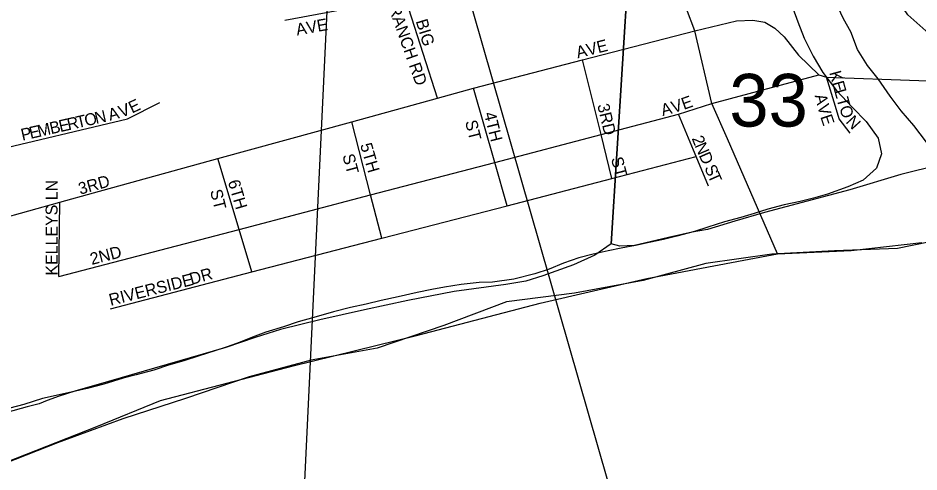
# Model space of a CAD drawing. Extents: x 0 to 34, y 0 to 22.
# Drawn here: x 4.109 to 4.825, y 15.627 to 15.987 of the extents above; entities that cross this region are included whole.
import ezdxf

# ---------------------------------------------------------------- set-up
doc = ezdxf.new("R2010")
doc.units = 0
for name, color, linetype in [('GM_X_City_Street', 7, 'Continuous'), ('GM_X_City_Street_Text', 7, 'Continuous'), ('GM_X_Corporation', 7, 'Continuous'), ('GM_X_County', 7, 'Continuous'), ('GM_X_Major_River', 7, 'Continuous'), ('GM_X_Section', 7, 'Continuous'), ('GM_X_Section_Text', 7, 'Continuous'), ('GM_X_State_Route', 7, 'Continuous'), ('GM_X_Township', 7, 'Continuous'), ('SH_Text', 7, 'Continuous')]:
    doc.layers.add(name, color=color, linetype=linetype)

msp = doc.modelspace()

# ---------------------------------------------------------------- linework, layer by layer
at = {"layer": 'GM_X_City_Street'}
for points in [[(4.86125, 15.93632), (4.85274, 15.94797), (4.84833, 15.95944), (4.83245, 15.97489), (4.81569, 15.9899), (4.80157, 16.01108), (4.79231, 16.02829), (4.78084, 16.05212), (4.76716, 16.07066), (4.75735, 16.07837), (4.75513, 16.07932), (4.7419, 16.085), (4.71334, 16.09156), (4.70852, 16.09155), (4.68605, 16.0915), (4.66482, 16.0903), (4.64496, 16.08968), (4.61963, 16.13871), (4.60617, 16.16446), (4.59926, 16.17803), (4.59104, 16.19418), (4.57912, 16.21207)], [(4.44235, 15.92357), (4.41948, 15.9945), (4.4089, 16.0181), (4.4039, 16.02506), (4.39749, 16.03163), (4.38508, 16.04152), (4.29, 16.06275), (4.24872, 16.07468)], [(4.32117, 15.98558), (4.38685, 15.99761)], [(4.44235, 15.92357), (4.47091, 15.93141), (4.55748, 15.95393), (4.64682, 15.97698)], [(4.58091, 15.85974), (4.57222, 15.89467), (4.55748, 15.95393)], [(4.14169, 15.78179), (4.28486, 15.81933), (4.38928, 15.8467), (4.48786, 15.87256), (4.57222, 15.89467), (4.63377, 15.91081), (4.66031, 15.91938), (4.74515, 15.94209)], [(4.75834, 15.91682), (4.75121, 15.94026)], [(4.49778, 15.83813), (4.48786, 15.87256), (4.47091, 15.93141)], [(4.08456, 15.88074), (4.19618, 15.90713), (4.22201, 15.92)], [(4.09304, 15.82718), (4.1424, 15.84105), (4.16933, 15.84846), (4.26803, 15.87561), (4.3744, 15.90487), (4.44235, 15.92357)], [(4.64568, 15.88228), (4.63377, 15.91081)], [(4.76999, 15.89571), (4.76128, 15.90714), (4.75834, 15.91682)], [(4.39809, 15.81223), (4.38928, 15.8467), (4.3744, 15.90487)], [(4.65758, 15.85374), (4.64782, 15.87712), (4.64568, 15.88228), (4.64568, 15.88228)], [(4.18263, 15.75624), (4.295, 15.78543), (4.39809, 15.81223), (4.49778, 15.83813), (4.58091, 15.85974), (4.64782, 15.87712)], [(4.295, 15.78543), (4.28486, 15.81933), (4.26803, 15.87561)], [(4.14169, 15.78179), (4.1424, 15.84105)]]:
    msp.add_lwpolyline(points, dxfattribs=at)
at = {"layer": 'GM_X_Corporation'}
msp.add_lwpolyline([(4.85824, 15.81444), (4.80773, 15.80402), (4.75763, 15.80234), (4.70791, 15.79952), (4.65552, 15.79216), (4.60575, 15.7787), (4.55106, 15.76868), (4.49715, 15.7617), (4.44736, 15.74292), (4.39453, 15.72492), (4.34213, 15.71527), (4.29274, 15.70219), (4.2422, 15.68494), (4.19242, 15.66882), (4.14073, 15.64967), (4.09056, 15.63014)], dxfattribs=at)
at = {"layer": 'GM_X_County'}
msp.add_lwpolyline([(4.09995, 15.63443), (4.17199, 15.66269), (4.22242, 15.6833), (4.32785, 15.71087), (4.42569, 15.73501), (4.52391, 15.76066), (4.60849, 15.78021), (4.68557, 15.79473), (4.71246, 15.79978), (4.77084, 15.80259), (4.82699, 15.80879)], dxfattribs=at)
at = {"layer": 'GM_X_Major_River'}
for points in [[(4.72161, 16.00319), (4.72848, 15.98423), (4.73343, 15.97134), (4.74067, 15.95693), (4.74828, 15.94405), (4.75929, 15.92966), (4.77183, 15.91603), (4.78283, 15.90505), (4.79233, 15.8918)], [(4.83058, 15.8885), (4.8207, 15.90175), (4.81044, 15.91349), (4.8017, 15.92523), (4.7922, 15.93887), (4.78384, 15.94947), (4.77586, 15.96235), (4.77052, 15.97638), (4.76481, 15.98661), (4.75872, 15.9995)], [(4.79233, 15.8918), (4.79502, 15.87928), (4.79089, 15.86788), (4.78032, 15.85836), (4.76822, 15.85301), (4.75196, 15.84726), (4.74099, 15.84419), (4.7304, 15.8415), (4.71753, 15.83881), (4.70467, 15.83535), (4.6937, 15.8319), (4.68312, 15.82883), (4.67025, 15.82538), (4.65702, 15.82116), (4.64643, 15.81771), (4.63243, 15.81387), (4.62184, 15.81119), (4.61049, 15.80887), (4.59952, 15.80656), (4.58817, 15.80425), (4.57796, 15.80232), (4.56585, 15.79963), (4.5545, 15.79656), (4.5424, 15.79234), (4.53106, 15.78776), (4.51972, 15.78392), (4.50307, 15.7797), (4.48605, 15.77737), (4.47545, 15.77696), (4.46107, 15.7754), (4.44783, 15.77346), (4.43799, 15.77153), (4.42626, 15.76922), (4.41113, 15.76575), (4.39751, 15.76268), (4.38579, 15.75998), (4.3733, 15.75729), (4.35968, 15.75383), (4.34418, 15.74923), (4.3317, 15.74577), (4.31997, 15.74194), (4.30598, 15.73773), (4.29539, 15.73352), (4.28556, 15.72969), (4.27535, 15.72587), (4.26552, 15.7228), (4.25228, 15.71859), (4.24094, 15.71476), (4.22884, 15.7113), (4.21711, 15.70747), (4.20312, 15.70363), (4.19291, 15.70095), (4.1774, 15.69634), (4.16416, 15.69289), (4.15243, 15.6902), (4.14184, 15.68789), (4.1286, 15.68481), (4.11385, 15.68021), (4.10288, 15.67714)]]:
    msp.add_lwpolyline(points, dxfattribs=at)
at = {"layer": 'GM_X_Section'}
for points in [[(3.50743, 16.08595), (4.59377, 16.02271), (4.58028, 15.80787), (4.56741, 15.79876), (4.55036, 15.79118), (4.52613, 15.78245), (4.51249, 15.77826), (4.49657, 15.7756), (4.45566, 15.76989), (4.41891, 15.76266), (4.38444, 15.75544), (4.34882, 15.74745), (4.31776, 15.73985), (4.29769, 15.7334), (4.2742, 15.72542), (4.18101, 15.69846), (4.15449, 15.69086), (4.14199, 15.68668), (4.13252, 15.68327), (4.12608, 15.68061), (4.11661, 15.67833), (4.07911, 15.66807)], [(4.8413, 15.87058), (4.81024, 15.86297), (4.7697, 15.85082), (4.70189, 15.83259), (4.67841, 15.82575), (4.65681, 15.81929), (4.64469, 15.81701), (4.62575, 15.81283), (4.59885, 15.80636), (4.58711, 15.80598), (4.58028, 15.80787), (4.59377, 16.02271), (5.23679, 15.98757)]]:
    msp.add_lwpolyline(points, dxfattribs=at)
at = {"layer": 'GM_X_State_Route'}
for points in [[(4.82457, 15.93763), (4.86125, 15.93632), (4.89421, 15.93426), (4.9215, 15.93426), (4.95086, 15.93499), (4.9678, 15.93881), (4.99473, 15.94584), (5.05575, 15.97631), (5.05991, 15.97837), (5.1536, 16.02489), (5.27058, 16.07147), (5.37835, 16.10837), (5.51744, 16.15908), (5.5266, 16.16226), (5.67496, 16.21375)], [(4.64682, 15.97698), (4.62693, 16.02973), (4.60641, 16.08067), (4.59597, 16.10951), (4.56509, 16.18055)], [(4.64682, 15.97698), (4.6797, 15.98505), (4.69283, 15.98562), (4.7024, 15.98405), (4.71024, 15.9792), (4.71767, 15.9722), (4.72895, 15.95778), (4.74515, 15.94209), (4.75121, 15.94026), (4.82457, 15.93763)], [(4.67257, 15.89127), (4.66031, 15.91938), (4.64682, 15.97698)], [(4.68853, 15.85467), (4.67257, 15.89127)], [(4.71246, 15.79978), (4.68853, 15.85467)]]:
    msp.add_lwpolyline(points, dxfattribs=at)
at = {"layer": 'GM_X_Township'}
msp.add_lwpolyline([(4.09995, 15.63443), (4.17199, 15.66269), (4.22242, 15.6833), (4.32785, 15.71087), (4.42569, 15.73501), (4.52391, 15.76066), (4.60849, 15.78021), (4.68557, 15.79473), (4.71246, 15.79978), (4.77084, 15.80259), (4.82699, 15.80879)], dxfattribs=at)
at = {"layer": 'SH_Text'}
msp.add_lwpolyline([(4.31689, 15.19549), (4.37122, 16.33865), (4.69914, 15.19549)], close=True, dxfattribs=at)

# ---------------------------------------------------------------- texts
at = {"layer": 'GM_X_City_Street_Text'}
for s, rotation, p in [('BRANCH RD', 289.5156, (4.40044, 16.0036)), ('AVE', 10.12447, (4.33084, 15.97332)), ('BIG', 286.92745, (4.425, 15.98479)), ('AVE', 14.0367, (4.55369, 15.95517)), ('K', 285.44215, (4.75335, 15.9439)), ('E', 285.4317, (4.75557, 15.93587)), ('E', 19.56795, (4.63796, 15.91421)), ('A', 284.53755, (4.74174, 15.92563)), ('L', 285.45024, (4.75734, 15.92944)), ('T', 285.4317, (4.75912, 15.92301)), ('V', 20.45121, (4.19118, 15.90802)), ('E', 25.53297, (4.19983, 15.91129)), ('3RD', 283.49694, (4.56919, 15.91802)), ('A', 15.04596, (4.62117, 15.90933)), ('V', 17.28323, (4.62961, 15.9116)), ('V', 285.11237, (4.74386, 15.91746)), ('O', 289.92163, (4.76114, 15.91581)), ('T', 12.82857, (4.15664, 15.89968)), ('O', 12.82857, (4.16314, 15.90116)), ('N', 12.82857, (4.17126, 15.90301)), ('A', 15.36945, (4.18227, 15.90553)), ('4TH', 284.03746, (4.47919, 15.91137)), ('E', 288.43702, (4.74621, 15.90884)), ('N', 312.69038, (4.7661, 15.90449)), ('M', 12.82857, (4.12576, 15.89265)), ('B', 12.82857, (4.13551, 15.89487)), ('E', 12.82857, (4.14282, 15.89654)), ('R', 12.82857, (4.14933, 15.89802)), ('ST', 284.04167, (4.46421, 15.90492)), ('P', 12.82857, (4.11276, 15.88969)), ('E', 12.82857, (4.11926, 15.89117)), ('2', 291.88477, (4.64411, 15.89159)), ('N', 293.04245, (4.64637, 15.88599)), ('5TH', 286.26004, (4.38083, 15.88644)), ('ST', 284.93732, (4.36677, 15.87803)), ('ST', 284.92349, (4.58001, 15.87556)), ('D', 293.77048, (4.64968, 15.8782)), ('S', 293.81631, (4.65405, 15.86828)), ('3RD', 15.64127, (4.15864, 15.84682)), ('T', 293.81964, (4.65675, 15.86218)), ('KELLEYS LN', 90, (4.14067, 15.7826)), ('6TH', 286.26019, (4.27583, 15.85727)), ('ST', 284.04167, (4.26171, 15.84992)), ('2ND', 14.53417, (4.16785, 15.791)), ('DR', 15.52247, (4.24698, 15.77515)), ('RIVERSIDE', 14.22531, (4.18285, 15.7585))]:
    msp.add_text(s, height=0.00947, rotation=rotation, dxfattribs=at).set_placement(p)
at = {"layer": 'GM_X_Section_Text'}
msp.add_text('33', height=0.041856, rotation=0.00001, dxfattribs=at).set_placement((4.67412, 15.901))

doc.saveas('drawing.dxf')
